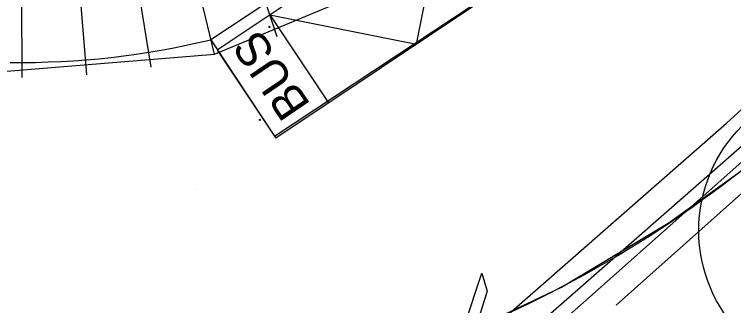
# Model space of a CAD drawing. Extents: x -438303 to -437792, y -1133191 to -1132731.
# Drawn here: x -438058.05 to -438041.04, y -1132976.36 to -1132969.48 of the extents above; entities that cross this region are included whole.
import ezdxf

# ---------------------------------------------------------------- set-up
doc = ezdxf.new("R2010")
doc.units = 0
for name, color, linetype in [('OSY', 7, 'Continuous'), ('SILNA 2', 7, 'Continuous'), ('Vrstva 1', 7, 'Continuous'), ('Vrstva 10', 7, 'Continuous'), ('Vrstva 11', 7, 'Continuous'), ('Vrstva 40', 7, 'Continuous'), ('Vrstva 9', 7, 'Continuous')]:
    doc.layers.add(name, color=color, linetype=linetype)

# ---------------------------------------------------------------- blocks, each defined once
blk = doc.blocks.new('A$C6C6266F8')
at = {"layer": 'OSY'}
for p, q in [((-45.52, -189.61), (-23.34, -97.24)), ((-30.5, -192.6), (-15.64, -98.77)), ((-15.3, -194.4), (-7.85, -99.69)), ((0, -195), (0, -100)), ((7.85, -99.69), (15.3, -194.4))]:
    blk.add_line(p, q, dxfattribs=at)

msp = doc.modelspace()

# ---------------------------------------------------------------- linework, layer by layer
at = {"layer": 'OSY'}
msp.add_lwpolyline([(-438050.489, -1132933.436), (-438056.425, -1132932.025), (-438062.506, -1132932.517), (-438068.137, -1132934.864), (-438072.767, -1132938.837), (-438075.944, -1132944.046), (-438077.355, -1132949.981), (-438076.862, -1132956.062), (-438074.515, -1132961.694), (-438070.543, -1132966.324), (-438065.334, -1132969.5), (-438059.398, -1132970.911), (-438053.317, -1132970.419), (-438047.686, -1132968.072), (-438043.055, -1132964.099), (-438039.879, -1132958.89), (-438038.468, -1132952.955), (-438038.96, -1132946.874), (-438041.308, -1132941.242), (-438045.28, -1132936.612)], close=True, dxfattribs=at)
at = {"layer": 'SILNA 2'}
msp.add_lwpolyline([(-438042.557, -1132962.908), (-438053.403, -1132970.075), (-438051.898, -1132972.353), (-438041.052, -1132965.186)], close=True, dxfattribs=at)
msp.add_lwpolyline([(-438042.557, -1132962.908), (-438053.403, -1132970.075), (-438051.898, -1132972.353), (-438041.052, -1132965.186)], close=True, dxfattribs=at)
at = {"layer": 'Vrstva 1'}
for p, q in [((-438042.439, -1132963.106), (-438053.254, -1132970.32)), ((-438042.439, -1132963.106), (-438053.254, -1132970.32)), ((-438041.052, -1132965.186), (-438051.867, -1132972.4)), ((-438041.052, -1132965.186), (-438051.867, -1132972.4)), ((-438052.006, -1132969.488), (-438050.619, -1132971.567)), ((-438052.006, -1132969.488), (-438050.619, -1132971.567)), ((-438053.254, -1132970.32), (-438051.867, -1132972.4)), ((-438053.254, -1132970.32), (-438051.867, -1132972.4)), ((-438041.204, -1132972.05), (-438041.204, -1132972.05)), ((-438053.757, -1132973.61), (-438053.757, -1132973.61)), ((-438043.816, -1132976.349), (-438043.816, -1132976.349))]:
    msp.add_line(p, q, dxfattribs=at)
msp.add_lwpolyline([(-438052.006, -1132969.488), (-438048.539, -1132970.18), (-438047.846, -1132966.713), (-438044.379, -1132967.406), (-438043.687, -1132963.939)], dxfattribs=at)
msp.add_lwpolyline([(-438052.006, -1132969.488), (-438048.539, -1132970.18), (-438047.846, -1132966.713), (-438044.379, -1132967.406), (-438043.687, -1132963.939)], dxfattribs=at)
for centre in [(-438052.017, -1132969.775), (-438052.017, -1132969.775), (-438052.242, -1132971.969), (-438052.242, -1132971.969)]:
    msp.add_circle(centre, 0.0127, dxfattribs=at)
for centre, radius, start, end in [((-438057.911, -1132951.468), 27.6, 285.1197, 325.2141), ((-438057.911, -1132951.468), 27.6, 285.1197, 325.2141), ((-438057.911, -1132951.464), 19.15, 269.2928, 283.6167), ((-438057.911, -1132951.464), 19.15, 269.2928, 283.6167)]:
    msp.add_arc(centre, radius, start, end, dxfattribs=at)
at = {"layer": 'Vrstva 10'}
msp.add_lwpolyline([(-438035.376, -1132968.181), (-438040.49, -1132972.647), (-438048.755, -1132979.99), (-438064.924, -1132994.417), (-438072.55, -1133001.015), (-438073.819, -1133001.824), (-438074.934, -1133002.283), (-438076.129, -1133002.536)], dxfattribs=at)
at = {"layer": 'Vrstva 11'}
for points in [[(-438073.846, -1133000.884), (-438049.346, -1132979.178), (-438041.204, -1132972.05), (-438034.947, -1132966.333)], [(-438064.679, -1132993.618), (-438048.923, -1132979.658), (-438040.777, -1132972.527), (-438034.481, -1132966.775)], [(-438045.482, -1132979.184), (-438047.4, -1132976.833), (-438046.991, -1132975.597), (-438046.863, -1132976.022), (-438047.068, -1132976.673), (-438047.4, -1132976.833)]]:
    msp.add_lwpolyline(points, dxfattribs=at)
at = {"layer": 'Vrstva 40'}
for points in [[(-438006.517, -1132950.825), (-438080.128, -1133015.753), (-438085.047, -1133011.675), (-438080.396, -1133006.399), (-438083.987, -1133003.228), (-438082.355, -1133001.381), (-438077.033, -1133005.821), (-438076.406, -1133006.347), (-438075.765, -1133005.58), (-438066.274, -1132994.076), (-438072.916, -1132988.399), (-438072.237, -1132987.605), (-438069.545, -1132989.828), (-438068.169, -1132988.18), (-438065.482, -1132990.423), (-438063.682, -1132988.266), (-438060.995, -1132990.509), (-438050.697, -1132978.171), (-438047.623, -1132977.126), (-438045.11, -1132975.925), (-438042.586, -1132974.412), (-438040.838, -1132973.158)], [(-438006.517, -1132950.825), (-438080.128, -1133015.753), (-438082.213, -1133013.389), (-438066.274, -1132994.076), (-438072.916, -1132988.399), (-438072.237, -1132987.605), (-438069.545, -1132989.828), (-438068.169, -1132988.18), (-438065.482, -1132990.423), (-438063.682, -1132988.266), (-438060.995, -1132990.509), (-438050.697, -1132978.171), (-438047.623, -1132977.126), (-438045.11, -1132975.925), (-438042.586, -1132974.412), (-438040.838, -1132973.158)]]:
    msp.add_lwpolyline(points, dxfattribs=at)
msp.add_circle((-438038.372, -1132974.584), 3.489, dxfattribs=at)
at = {"layer": 'Vrstva 9'}
msp.add_lwpolyline([(-438034.189, -1132967.884), (-438040.121, -1132973.067), (-438043.816, -1132976.349)], dxfattribs=at)

# ---------------------------------------------------------------- block references
at = {"layer": 'OSY', "xscale": 0.10000000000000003, "yscale": 0.10000000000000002, "rotation": 13.627557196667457}
msp.add_blockref('A$C6C6266F8', (-438057.911, -1132951.468), dxfattribs=at)

# ---------------------------------------------------------------- texts
at = {"layer": 'Vrstva 1'}
msp.add_text('BUS', height=0.8, rotation=124.2114, dxfattribs=at).set_placement((-438051.027, -1132971.615))
msp.add_text('BUS', height=0.8, rotation=124.2114, dxfattribs=at).set_placement((-438051.027, -1132971.615))

doc.saveas('drawing.dxf')
